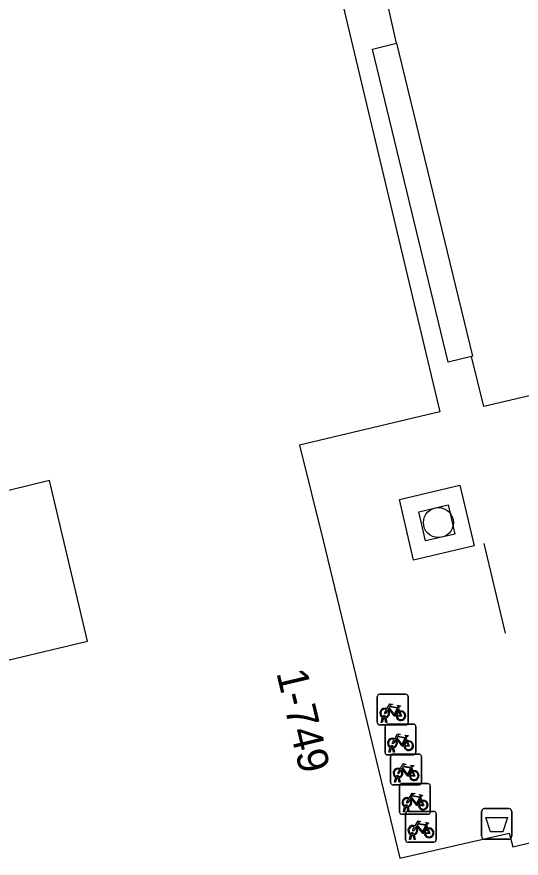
# Model space of a CAD drawing. Extents: x 160676 to 161153, y 383244 to 383713.
# Drawn here: x 160908.82 to 160925.21, y 383491.7 to 383519.05 of the extents above; entities that cross this region are included whole.
import ezdxf

# ---------------------------------------------------------------- set-up
doc = ezdxf.new("R2010")
doc.units = 0
for name, color, linetype in [('IMGEO_Afvalbak', 7, 'Continuous'), ('IMGEO_Boom', 7, 'Continuous'), ('IMGEO_Fietsenrek', 7, 'Continuous'), ('IMGEO_Lijnafwatering', 7, 'Continuous'), ('IMGEO_Muur', 7, 'Continuous'), ('IMGEO_Pand', 7, 'Continuous'), ('IMGEO_Pand_nummerreeks', 7, 'Continuous'), ('IMGEO_Parkeervlak_open', 7, 'Continuous'), ('IMGEO_Voetpad_open', 7, 'Continuous')]:
    doc.layers.add(name, color=color, linetype=linetype)

msp = doc.modelspace()

# ---------------------------------------------------------------- linework, layer by layer
at = {"layer": 'IMGEO_Afvalbak'}
for p, q in [((160923.922, 383492.41), (160923.922, 383493.21)), ((160923.922, 383493.21), (160923.922, 383492.41)), ((160924.022, 383493.31), (160924.812, 383493.31)), ((160924.812, 383493.31), (160924.022, 383493.31)), ((160924.912, 383493.21), (160924.912, 383492.41)), ((160924.912, 383492.41), (160924.912, 383493.21)), ((160924.812, 383492.31), (160924.022, 383492.31)), ((160924.022, 383492.31), (160924.812, 383492.31))]:
    msp.add_line(p, q, dxfattribs=at)
msp.add_lwpolyline([(160924.065, 383493.024), (160924.769, 383493.024), (160924.62, 383492.554), (160924.214, 383492.554), (160924.065, 383493.024)], dxfattribs=at)
for centre, start, end in [((160924.022, 383493.21), 90, 180), ((160924.022, 383493.21), 90, 180), ((160924.812, 383493.21), 0, 90), ((160924.812, 383493.21), 360, 90), ((160924.022, 383492.41), 180, 270), ((160924.022, 383492.41), 180, 270), ((160924.812, 383492.41), 270, 0), ((160924.812, 383492.41), 270, 0)]:
    msp.add_arc(centre, 0.1, start, end, dxfattribs=at)
at = {"layer": 'IMGEO_Boom'}
msp.add_circle((160922.524, 383502.608), 0.489, dxfattribs=at)
at = {"layer": 'IMGEO_Fietsenrek'}
for p, q in [((160920.612, 383497.028), (160921.453, 383497.028)), ((160921.453, 383497.028), (160920.612, 383497.028)), ((160920.537, 383496.103), (160920.537, 383496.944)), ((160920.537, 383496.944), (160920.537, 383496.103)), ((160921.537, 383496.953), (160921.537, 383496.112)), ((160921.537, 383496.112), (160921.537, 383496.953)), ((160921.224, 383496.577), (160921.26, 383496.482)), ((160920.664, 383496.112), (160920.703, 383496.272)), ((160920.733, 383496.26), (160920.698, 383496.112)), ((160920.775, 383496.284), (160920.774, 383496.288)), ((160920.816, 383496.112), (160920.782, 383496.254)), ((160920.806, 383496.295), (160920.807, 383496.288)), ((160920.814, 383496.258), (160920.849, 383496.112)), ((160921.462, 383496.028), (160920.621, 383496.028)), ((160920.621, 383496.028), (160921.462, 383496.028)), ((160920.698, 383496.112), (160920.664, 383496.112)), ((160920.789, 383495.13), (160920.789, 383495.971)), ((160920.789, 383495.971), (160920.789, 383495.13)), ((160920.849, 383496.112), (160920.816, 383496.112)), ((160920.864, 383496.055), (160921.705, 383496.055)), ((160921.705, 383496.055), (160920.864, 383496.055)), ((160921.789, 383495.98), (160921.789, 383495.139)), ((160921.789, 383495.139), (160921.789, 383495.98)), ((160921.476, 383495.604), (160921.512, 383495.509)), ((160920.916, 383495.139), (160920.955, 383495.299)), ((160920.95, 383495.139), (160920.916, 383495.139)), ((160920.985, 383495.287), (160920.95, 383495.139)), ((160921.027, 383495.311), (160921.026, 383495.315)), ((160921.068, 383495.139), (160921.034, 383495.281)), ((160921.045, 383495.081), (160921.886, 383495.081)), ((160921.886, 383495.081), (160921.045, 383495.081)), ((160921.058, 383495.322), (160921.059, 383495.315)), ((160921.066, 383495.285), (160921.101, 383495.139)), ((160921.101, 383495.139), (160921.068, 383495.139)), ((160921.714, 383495.055), (160920.873, 383495.055)), ((160920.873, 383495.055), (160921.714, 383495.055)), ((160920.97, 383494.156), (160920.97, 383494.997)), ((160920.97, 383494.997), (160920.97, 383494.156)), ((160921.97, 383495.006), (160921.97, 383494.165)), ((160921.97, 383494.165), (160921.97, 383495.006)), ((160921.657, 383494.63), (160921.693, 383494.535)), ((160921.097, 383494.165), (160921.136, 383494.325)), ((160921.166, 383494.313), (160921.131, 383494.165)), ((160921.208, 383494.337), (160921.207, 383494.341)), ((160921.249, 383494.165), (160921.215, 383494.307)), ((160921.239, 383494.348), (160921.24, 383494.341)), ((160921.247, 383494.311), (160921.282, 383494.165)), ((160921.895, 383494.081), (160921.054, 383494.081)), ((160921.054, 383494.081), (160921.895, 383494.081)), ((160921.131, 383494.165), (160921.097, 383494.165)), ((160921.282, 383494.165), (160921.249, 383494.165)), ((160921.259, 383493.198), (160921.259, 383494.039)), ((160921.259, 383494.039), (160921.259, 383493.198)), ((160921.334, 383494.123), (160922.175, 383494.123)), ((160922.175, 383494.123), (160921.334, 383494.123)), ((160922.259, 383494.048), (160922.259, 383493.207)), ((160922.259, 383493.207), (160922.259, 383494.048)), ((160921.946, 383493.672), (160921.982, 383493.577)), ((160921.386, 383493.207), (160921.425, 383493.367)), ((160921.42, 383493.207), (160921.386, 383493.207)), ((160921.455, 383493.355), (160921.42, 383493.207)), ((160921.497, 383493.379), (160921.496, 383493.383)), ((160921.538, 383493.207), (160921.504, 383493.349)), ((160921.528, 383493.39), (160921.529, 383493.383)), ((160921.528, 383493.218), (160922.369, 383493.218)), ((160922.369, 383493.218), (160921.528, 383493.218)), ((160921.536, 383493.353), (160921.571, 383493.207)), ((160921.571, 383493.207), (160921.538, 383493.207)), ((160922.184, 383493.123), (160921.343, 383493.123)), ((160921.343, 383493.123), (160922.184, 383493.123)), ((160921.453, 383492.293), (160921.453, 383493.134)), ((160921.453, 383493.134), (160921.453, 383492.293)), ((160922.453, 383493.143), (160922.453, 383492.302)), ((160922.453, 383492.302), (160922.453, 383493.143)), ((160922.14, 383492.767), (160922.176, 383492.672)), ((160921.58, 383492.302), (160921.619, 383492.462)), ((160921.649, 383492.45), (160921.614, 383492.302)), ((160921.691, 383492.474), (160921.69, 383492.478)), ((160921.732, 383492.302), (160921.698, 383492.444)), ((160921.722, 383492.485), (160921.723, 383492.478)), ((160921.73, 383492.448), (160921.765, 383492.302)), ((160922.378, 383492.218), (160921.537, 383492.218)), ((160921.537, 383492.218), (160922.378, 383492.218)), ((160921.614, 383492.302), (160921.58, 383492.302)), ((160921.765, 383492.302), (160921.732, 383492.302))]:
    msp.add_line(p, q, dxfattribs=at)
for points in [[(160920.85, 383496.554), (160920.945, 383496.718), (160921.031, 383496.704), (160921.033, 383496.695), (160920.977, 383496.684), (160920.95, 383496.639), (160921.206, 383496.598)], [(160920.871, 383496.502), (160920.819, 383496.412), (160920.779, 383496.387), (160920.78, 383496.434), (160920.835, 383496.528)], [(160921.146, 383496.31), (160921.096, 383496.31), (160920.905, 383496.561), (160920.886, 383496.529)], [(160921.193, 383496.573), (160920.936, 383496.614), (160920.919, 383496.585), (160921.086, 383496.365), (160921.193, 383496.573)], [(160921.241, 383496.475), (160921.211, 383496.552), (160921.102, 383496.334), (160921.145, 383496.334)], [(160921.175, 383496.334), (160921.295, 383496.333), (160921.251, 383496.447)], [(160921.271, 383496.454), (160921.326, 383496.309), (160921.176, 383496.309)], [(160921.206, 383496.598), (160921.231, 383496.647), (160921.225, 383496.651), (160921.202, 383496.655), (160921.19, 383496.662), (160921.189, 383496.665), (160921.191, 383496.67), (160921.286, 383496.655), (160921.288, 383496.645), (160921.278, 383496.632), (160921.266, 383496.626), (160921.252, 383496.632), (160921.224, 383496.577)], [(160921.102, 383495.581), (160921.197, 383495.745), (160921.283, 383495.731), (160921.285, 383495.722), (160921.229, 383495.711), (160921.202, 383495.666), (160921.458, 383495.625)], [(160921.445, 383495.6), (160921.188, 383495.641), (160921.171, 383495.612), (160921.338, 383495.392), (160921.445, 383495.6)], [(160921.458, 383495.625), (160921.483, 383495.674), (160921.477, 383495.678), (160921.454, 383495.682), (160921.442, 383495.689), (160921.441, 383495.692), (160921.443, 383495.697), (160921.538, 383495.682), (160921.54, 383495.672), (160921.53, 383495.659), (160921.518, 383495.653), (160921.504, 383495.659), (160921.476, 383495.604)], [(160921.123, 383495.529), (160921.071, 383495.439), (160921.031, 383495.414), (160921.032, 383495.461), (160921.087, 383495.555)], [(160921.398, 383495.337), (160921.348, 383495.337), (160921.157, 383495.588), (160921.138, 383495.556)], [(160921.493, 383495.502), (160921.463, 383495.579), (160921.354, 383495.361), (160921.397, 383495.361)], [(160921.427, 383495.361), (160921.547, 383495.36), (160921.503, 383495.474)], [(160921.523, 383495.481), (160921.578, 383495.336), (160921.428, 383495.336)], [(160921.304, 383494.555), (160921.252, 383494.465), (160921.212, 383494.44), (160921.213, 383494.487), (160921.268, 383494.581)], [(160921.283, 383494.607), (160921.378, 383494.771), (160921.464, 383494.757), (160921.466, 383494.748), (160921.41, 383494.737), (160921.383, 383494.692), (160921.639, 383494.651)], [(160921.579, 383494.363), (160921.529, 383494.363), (160921.338, 383494.614), (160921.319, 383494.582)], [(160921.626, 383494.626), (160921.369, 383494.667), (160921.352, 383494.638), (160921.519, 383494.418), (160921.626, 383494.626)], [(160921.674, 383494.528), (160921.644, 383494.605), (160921.535, 383494.387), (160921.578, 383494.387)], [(160921.639, 383494.651), (160921.664, 383494.7), (160921.658, 383494.704), (160921.635, 383494.708), (160921.623, 383494.715), (160921.622, 383494.718), (160921.624, 383494.723), (160921.719, 383494.708), (160921.721, 383494.698), (160921.711, 383494.685), (160921.699, 383494.679), (160921.685, 383494.685), (160921.657, 383494.63)], [(160921.608, 383494.387), (160921.728, 383494.386), (160921.684, 383494.5)], [(160921.704, 383494.507), (160921.759, 383494.362), (160921.609, 383494.362)], [(160921.572, 383493.649), (160921.667, 383493.813), (160921.753, 383493.799), (160921.755, 383493.79), (160921.699, 383493.779), (160921.672, 383493.734), (160921.928, 383493.693)], [(160921.915, 383493.668), (160921.658, 383493.709), (160921.641, 383493.68), (160921.808, 383493.46), (160921.915, 383493.668)], [(160921.928, 383493.693), (160921.953, 383493.742), (160921.947, 383493.746), (160921.924, 383493.75), (160921.912, 383493.757), (160921.911, 383493.76), (160921.913, 383493.765), (160922.008, 383493.75), (160922.01, 383493.74), (160922, 383493.727), (160921.988, 383493.721), (160921.974, 383493.727), (160921.946, 383493.672)], [(160921.593, 383493.597), (160921.541, 383493.507), (160921.501, 383493.482), (160921.502, 383493.529), (160921.557, 383493.623)], [(160921.868, 383493.405), (160921.818, 383493.405), (160921.627, 383493.656), (160921.608, 383493.624)], [(160921.963, 383493.57), (160921.933, 383493.647), (160921.824, 383493.429), (160921.867, 383493.429)], [(160921.897, 383493.429), (160922.017, 383493.428), (160921.973, 383493.542)], [(160921.993, 383493.549), (160922.048, 383493.404), (160921.898, 383493.404)], [(160921.766, 383492.744), (160921.861, 383492.908), (160921.947, 383492.894), (160921.949, 383492.885), (160921.893, 383492.874), (160921.866, 383492.829), (160922.122, 383492.788)], [(160921.787, 383492.692), (160921.735, 383492.602), (160921.695, 383492.577), (160921.696, 383492.624), (160921.751, 383492.718)], [(160922.062, 383492.5), (160922.012, 383492.5), (160921.821, 383492.751), (160921.802, 383492.719)], [(160922.109, 383492.763), (160921.852, 383492.804), (160921.835, 383492.775), (160922.002, 383492.555), (160922.109, 383492.763)], [(160922.157, 383492.665), (160922.127, 383492.742), (160922.018, 383492.524), (160922.061, 383492.524)], [(160922.091, 383492.524), (160922.211, 383492.523), (160922.167, 383492.637)], [(160922.187, 383492.644), (160922.242, 383492.499), (160922.092, 383492.499)], [(160922.122, 383492.788), (160922.147, 383492.837), (160922.141, 383492.841), (160922.118, 383492.845), (160922.106, 383492.852), (160922.105, 383492.855), (160922.107, 383492.86), (160922.202, 383492.845), (160922.204, 383492.835), (160922.194, 383492.822), (160922.182, 383492.816), (160922.168, 383492.822), (160922.14, 383492.767)]]:
    msp.add_lwpolyline(points, dxfattribs=at)
for centre, radius, start, end in [((160920.615, 383496.95), 0.0779, 92.4484, 184.2845), ((160920.615, 383496.95), 0.0779, 92.4484, 184.2845), ((160921.459, 383496.95), 0.0779, 2.4484, 94.2845), ((160921.459, 383496.95), 0.0779, 2.4484, 94.2845), ((160920.777, 383496.413), 0.159, 62.6766, 242.1369), ((160920.777, 383496.413), 0.129, 63.3192, 238.903), ((160920.777, 383496.413), 0.129, 283.6043, 43.4302), ((160920.777, 383496.413), 0.159, 283.5766, 46.6042), ((160921.304, 383496.329), 0.159, 113.3408, 178.3217), ((160921.304, 383496.329), 0.159, 187.0065, 105.7708), ((160921.304, 383496.329), 0.129, 113.923, 177.9556), ((160921.304, 383496.329), 0.129, 188.6715, 104.5883), ((160920.757, 383496.284), 0.0499, 12.8025, 158.6934), ((160920.777, 383496.413), 0.159, 253.9967, 271.7867), ((160920.757, 383496.284), 0.0174, 12.8025, 163.4502), ((160920.777, 383496.413), 0.129, 253.415, 269.0204), ((160920.615, 383496.106), 0.0779, 182.4484, 274.2845), ((160920.615, 383496.106), 0.0779, 182.4484, 274.2845), ((160920.867, 383495.977), 0.0779, 92.4484, 184.2845), ((160920.867, 383495.977), 0.0779, 92.4484, 184.2845), ((160921.459, 383496.106), 0.0779, 272.4484, 4.2845), ((160921.459, 383496.106), 0.0779, 272.4484, 4.2845), ((160921.711, 383495.977), 0.0779, 2.4484, 94.2845), ((160921.711, 383495.977), 0.0779, 2.4484, 94.2845), ((160921.029, 383495.44), 0.159, 62.6766, 242.1369), ((160921.029, 383495.44), 0.129, 63.3192, 238.903), ((160921.009, 383495.311), 0.0499, 12.8025, 158.6934), ((160921.029, 383495.44), 0.129, 283.6043, 43.4302), ((160921.029, 383495.44), 0.159, 283.5766, 46.6042), ((160921.556, 383495.356), 0.159, 113.3408, 178.3217), ((160921.556, 383495.356), 0.159, 187.0065, 105.7708), ((160921.556, 383495.356), 0.129, 113.923, 177.9556), ((160921.556, 383495.356), 0.129, 188.6715, 104.5883), ((160920.867, 383495.133), 0.0779, 182.4484, 274.2845), ((160920.867, 383495.133), 0.0779, 182.4484, 274.2845), ((160921.048, 383495.003), 0.0779, 92.4484, 184.2845), ((160921.048, 383495.003), 0.0779, 92.4484, 184.2845), ((160921.029, 383495.44), 0.159, 253.9967, 271.7867), ((160921.009, 383495.311), 0.0174, 12.8025, 163.4502), ((160921.029, 383495.44), 0.129, 253.415, 269.0204), ((160921.711, 383495.133), 0.0779, 272.4484, 4.2845), ((160921.711, 383495.133), 0.0779, 272.4484, 4.2845), ((160921.892, 383495.003), 0.0779, 2.4484, 94.2845), ((160921.892, 383495.003), 0.0779, 2.4484, 94.2845), ((160921.21, 383494.466), 0.159, 62.6766, 242.1369), ((160921.21, 383494.466), 0.129, 63.3192, 238.903), ((160921.21, 383494.466), 0.129, 283.6043, 43.4302), ((160921.21, 383494.466), 0.159, 283.5766, 46.6042), ((160921.737, 383494.382), 0.159, 113.3408, 178.3217), ((160921.737, 383494.382), 0.159, 187.0065, 105.7708), ((160921.19, 383494.337), 0.0499, 12.8025, 158.6934), ((160921.21, 383494.466), 0.159, 253.9967, 271.7867), ((160921.19, 383494.337), 0.0174, 12.8025, 163.4502), ((160921.21, 383494.466), 0.129, 253.415, 269.0204), ((160921.737, 383494.382), 0.129, 113.923, 177.9556), ((160921.737, 383494.382), 0.129, 188.6715, 104.5883), ((160921.048, 383494.159), 0.0779, 182.4484, 274.2845), ((160921.048, 383494.159), 0.0779, 182.4484, 274.2845), ((160921.337, 383494.045), 0.0779, 92.4484, 184.2845), ((160921.337, 383494.045), 0.0779, 92.4484, 184.2845), ((160921.892, 383494.159), 0.0779, 272.4484, 4.2845), ((160921.892, 383494.159), 0.0779, 272.4484, 4.2845), ((160922.181, 383494.045), 0.0779, 2.4484, 94.2845), ((160922.181, 383494.045), 0.0779, 2.4484, 94.2845), ((160921.499, 383493.508), 0.159, 62.6766, 242.1369), ((160921.499, 383493.508), 0.129, 63.3192, 238.903), ((160921.479, 383493.379), 0.0499, 12.8025, 158.6934), ((160921.499, 383493.508), 0.129, 283.6043, 43.4302), ((160921.499, 383493.508), 0.159, 283.5766, 46.6042), ((160922.026, 383493.424), 0.159, 113.3408, 178.3217), ((160922.026, 383493.424), 0.159, 187.0065, 105.7708), ((160922.026, 383493.424), 0.129, 113.923, 177.9556), ((160922.026, 383493.424), 0.129, 188.6715, 104.5883), ((160921.337, 383493.201), 0.0779, 182.4484, 274.2845), ((160921.337, 383493.201), 0.0779, 182.4484, 274.2845), ((160921.531, 383493.14), 0.0779, 92.4484, 184.2845), ((160921.531, 383493.14), 0.0779, 92.4484, 184.2845), ((160921.499, 383493.508), 0.159, 253.9967, 271.7867), ((160921.479, 383493.379), 0.0174, 12.8025, 163.4502), ((160921.499, 383493.508), 0.129, 253.415, 269.0204), ((160922.181, 383493.201), 0.0779, 272.4484, 4.2845), ((160922.181, 383493.201), 0.0779, 272.4484, 4.2845), ((160922.375, 383493.14), 0.0779, 2.4484, 94.2845), ((160922.375, 383493.14), 0.0779, 2.4484, 94.2845), ((160921.693, 383492.603), 0.159, 62.6766, 242.1369), ((160921.693, 383492.603), 0.129, 63.3192, 238.903), ((160921.693, 383492.603), 0.129, 283.6043, 43.4302), ((160921.693, 383492.603), 0.159, 283.5766, 46.6042), ((160922.22, 383492.519), 0.159, 113.3408, 178.3217), ((160922.22, 383492.519), 0.159, 187.0065, 105.7708), ((160922.22, 383492.519), 0.129, 113.923, 177.9556), ((160922.22, 383492.519), 0.129, 188.6715, 104.5883), ((160921.673, 383492.474), 0.0499, 12.8025, 158.6934), ((160921.693, 383492.603), 0.159, 253.9967, 271.7867), ((160921.673, 383492.474), 0.0174, 12.8025, 163.4502), ((160921.693, 383492.603), 0.129, 253.415, 269.0204), ((160921.531, 383492.296), 0.0779, 182.4484, 274.2845), ((160921.531, 383492.296), 0.0779, 182.4484, 274.2845), ((160922.375, 383492.296), 0.0779, 272.4484, 4.2845), ((160922.375, 383492.296), 0.0779, 272.4484, 4.2845)]:
    msp.add_arc(centre, radius, start, end, dxfattribs=at)
at = {"layer": 'IMGEO_Lijnafwatering'}
msp.add_lwpolyline([(160924.005, 383501.931), (160924.693, 383499.009)], dxfattribs=at)
at = {"layer": 'IMGEO_Muur'}
for points in [[(160923.223, 383503.825), (160923.686, 383501.848), (160921.718, 383501.387), (160921.255, 383503.364), (160923.223, 383503.825)], [(160922.102, 383502.012), (160921.883, 383502.963), (160922.841, 383503.183), (160923.06, 383502.233), (160922.102, 383502.012)]]:
    msp.add_lwpolyline(points, dxfattribs=at)
at = {"layer": 'IMGEO_Pand'}
for points in [[(160914.955, 383543.48), (160913.765, 383543.194), (160922.567, 383506.212), (160918.011, 383505.128), (160918.775, 383502.03), (160921.273, 383491.697), (160924.82, 383492.508), (160924.945, 383492.067), (160930.969, 383493.5)], [(160907.562, 383497.909), (160911.114, 383498.753), (160909.883, 383503.976), (160906.697, 383503.194), (160905.085, 383509.775), (160897.386, 383507.933)]]:
    msp.add_lwpolyline(points, dxfattribs=at)
at = {"layer": 'IMGEO_Parkeervlak_open'}
msp.add_lwpolyline([(160921.166, 383518.194), (160923.632, 383508.016), (160923.604, 383508.009)], dxfattribs=at)
at = {"layer": 'IMGEO_Voetpad_open'}
for points in [[(160921.166, 383518.194), (160920.797, 383519.84)], [(160923.604, 383508.009), (160922.842, 383507.825), (160920.376, 383518.003), (160921.166, 383518.194)], [(160928.346, 383507.404), (160923.998, 383506.38), (160923.604, 383508.009)]]:
    msp.add_lwpolyline(points, dxfattribs=at)

# ---------------------------------------------------------------- texts
at = {"layer": 'IMGEO_Pand_nummerreeks'}
msp.add_text('1-749', height=1, rotation=283.3898, dxfattribs=at).set_placement((160917.251, 383497.727))

doc.saveas('drawing.dxf')
